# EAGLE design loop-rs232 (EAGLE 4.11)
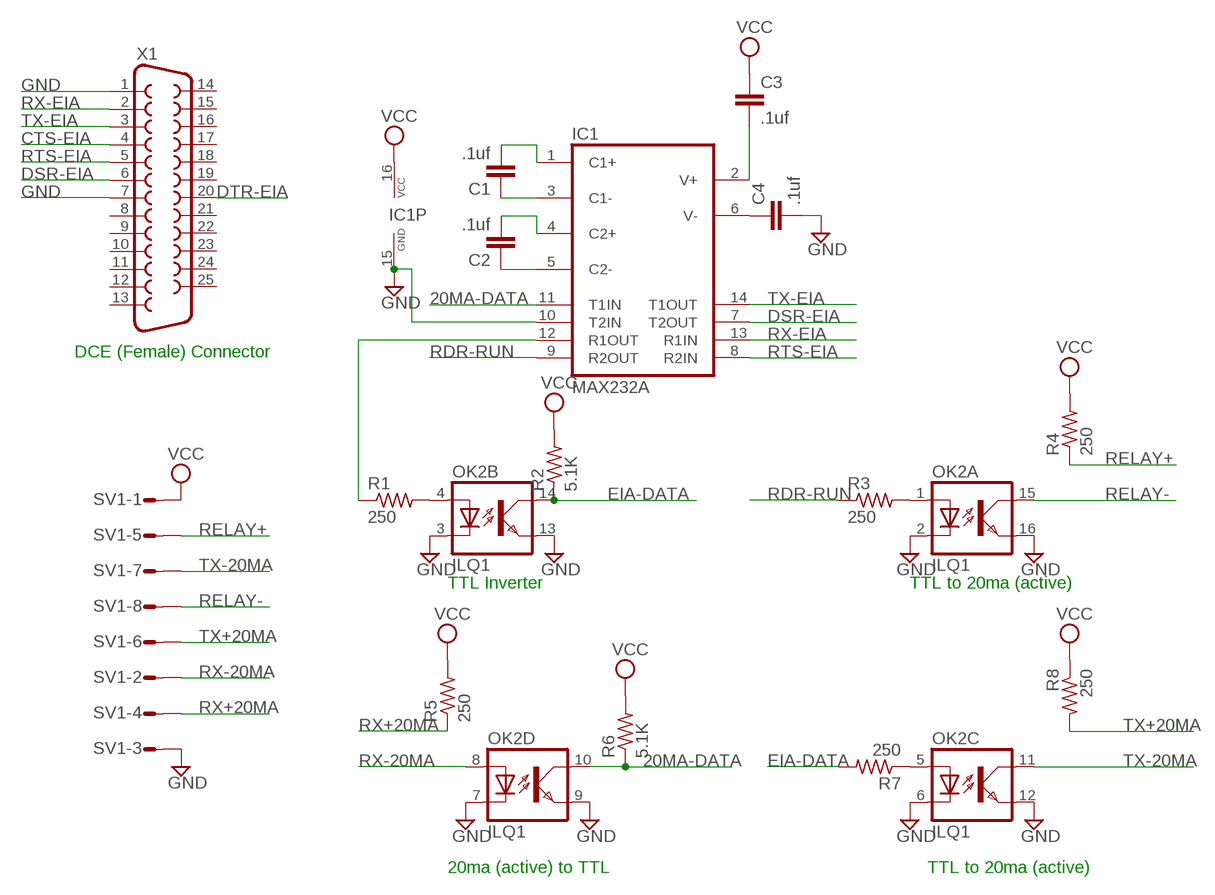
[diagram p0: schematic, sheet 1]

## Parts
C1  .1uf  C-EU050-025X075  [C050-025X075]
C2  .1uf  C-EU050-025X075  [C050-025X075]
C3  .1uf  C-EU050-025X075  [C050-025X075]
C4  .1uf  C-EU050-025X075  [C050-025X075]
IC1  MAX232A  MAX232  [DIL16]
OK2  ILQ1  [DIL16]
R1  250  R-US_0207/10  [0207/10]
R2  5.1K  R-US_0207/10  [0207/10]
R3  250  R-US_0207/10  [0207/10]
R4  250  R-US_0207/10  [0207/10]
R5  250  R-US_0207/10  [0207/10]
R6  5.1K  R-US_0207/10  [0207/10]
R7  250  R-US_0207/10  [0207/10]
R8  250  R-US_0207/10  [0207/10]
SV1  S08P  [S08P]
X1  F25H  [F25H]

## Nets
20MA-DATA: IC1.11(T1IN) OK2.10(D:COL) R6.1
CTS-EIA: X1.4
DSR-EIA: IC1.7(T2OUT) X1.6
DTR-EIA: X1.20
EIA-DATA: OK2.14(B:COL) R2.1 R7.2
GND: C4.2 IC1.10(T2IN) IC1.15(GND) OK2.2(A:C) OK2.3(B:C) OK2.6(C:C) OK2.7(D:C) OK2.9(D:EMIT) OK2.12(C:EMIT) OK2.13(B:EMIT) OK2.16(A:EMIT) SV1.3 X1.1 X1.7
N$1: C2.1 IC1.5(C2-)
N$2: C2.2 IC1.4(C2+)
N$3: C1.2 IC1.1(C1+)
N$4: C1.1 IC1.3(C1-)
N$8: IC1.12(R1OUT) R1.1
N$9: C3.2 IC1.2(V+)
N$10: C4.1 IC1.6(V-)
N$11: OK2.4(B:A) R1.2
N$12: OK2.1(A:A) R3.2
N$15: OK2.5(C:A) R7.1
RDR-RUN: IC1.9(R2OUT) R3.1
RELAY+: R4.1 SV1.5
RELAY-: OK2.15(A:COL) SV1.8
RTS-EIA: IC1.8(R2IN) X1.5
RX+20MA: R5.1 SV1.4
RX-20MA: OK2.8(D:A) SV1.2
RX-EIA: IC1.13(R1IN) X1.2
TX+20MA: R8.2 SV1.6
TX-20MA: OK2.11(C:COL) SV1.7
TX-EIA: IC1.14(T1OUT) X1.3
VCC: C3.1 IC1.16(VCC) R2.2 R4.2 R5.2 R6.2 R8.1 SV1.1
Unconnected: X1.8 X1.9 X1.10 X1.11 X1.12 X1.13 X1.14 X1.15 X1.16 X1.17 X1.18 X1.19 X1.21 X1.22 X1.23 X1.24 X1.25

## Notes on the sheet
- DCE (Female) Connector
- TTL Inverter | TTL to 20ma (active)
- 20ma (active) to TTL | TTL to 20ma (active)

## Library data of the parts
C1-C4 = rcl:C-EU: CAPACITOR, European symbol
IC1 = maxim:MAX232: RS232 TRANSEIVER
OK2 = optocoupler:ILQ1: SIEMENS OPTO COUPLER
R1-R8 = rcl:R-US_: RESISTOR, American symbol
SV1 = con-amp-mt:S08P: AMP MT CONNECTOR
X1 = con-subd:F25: SUB-D

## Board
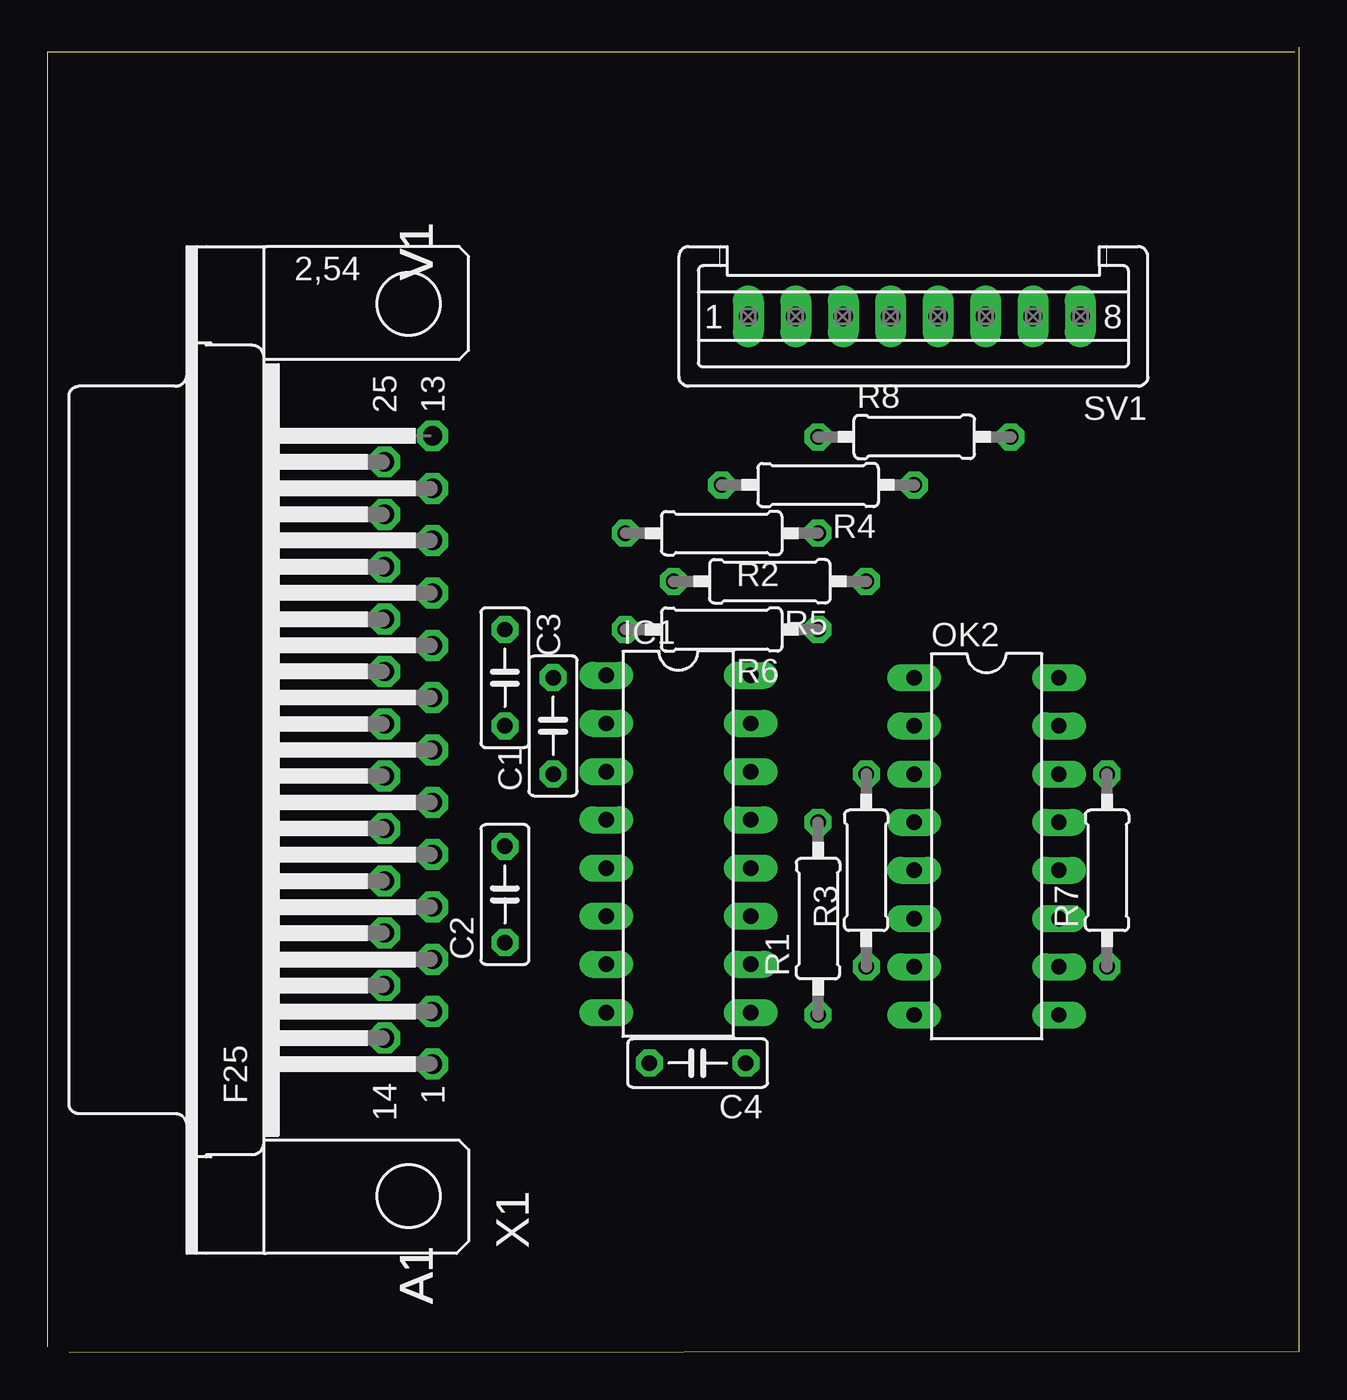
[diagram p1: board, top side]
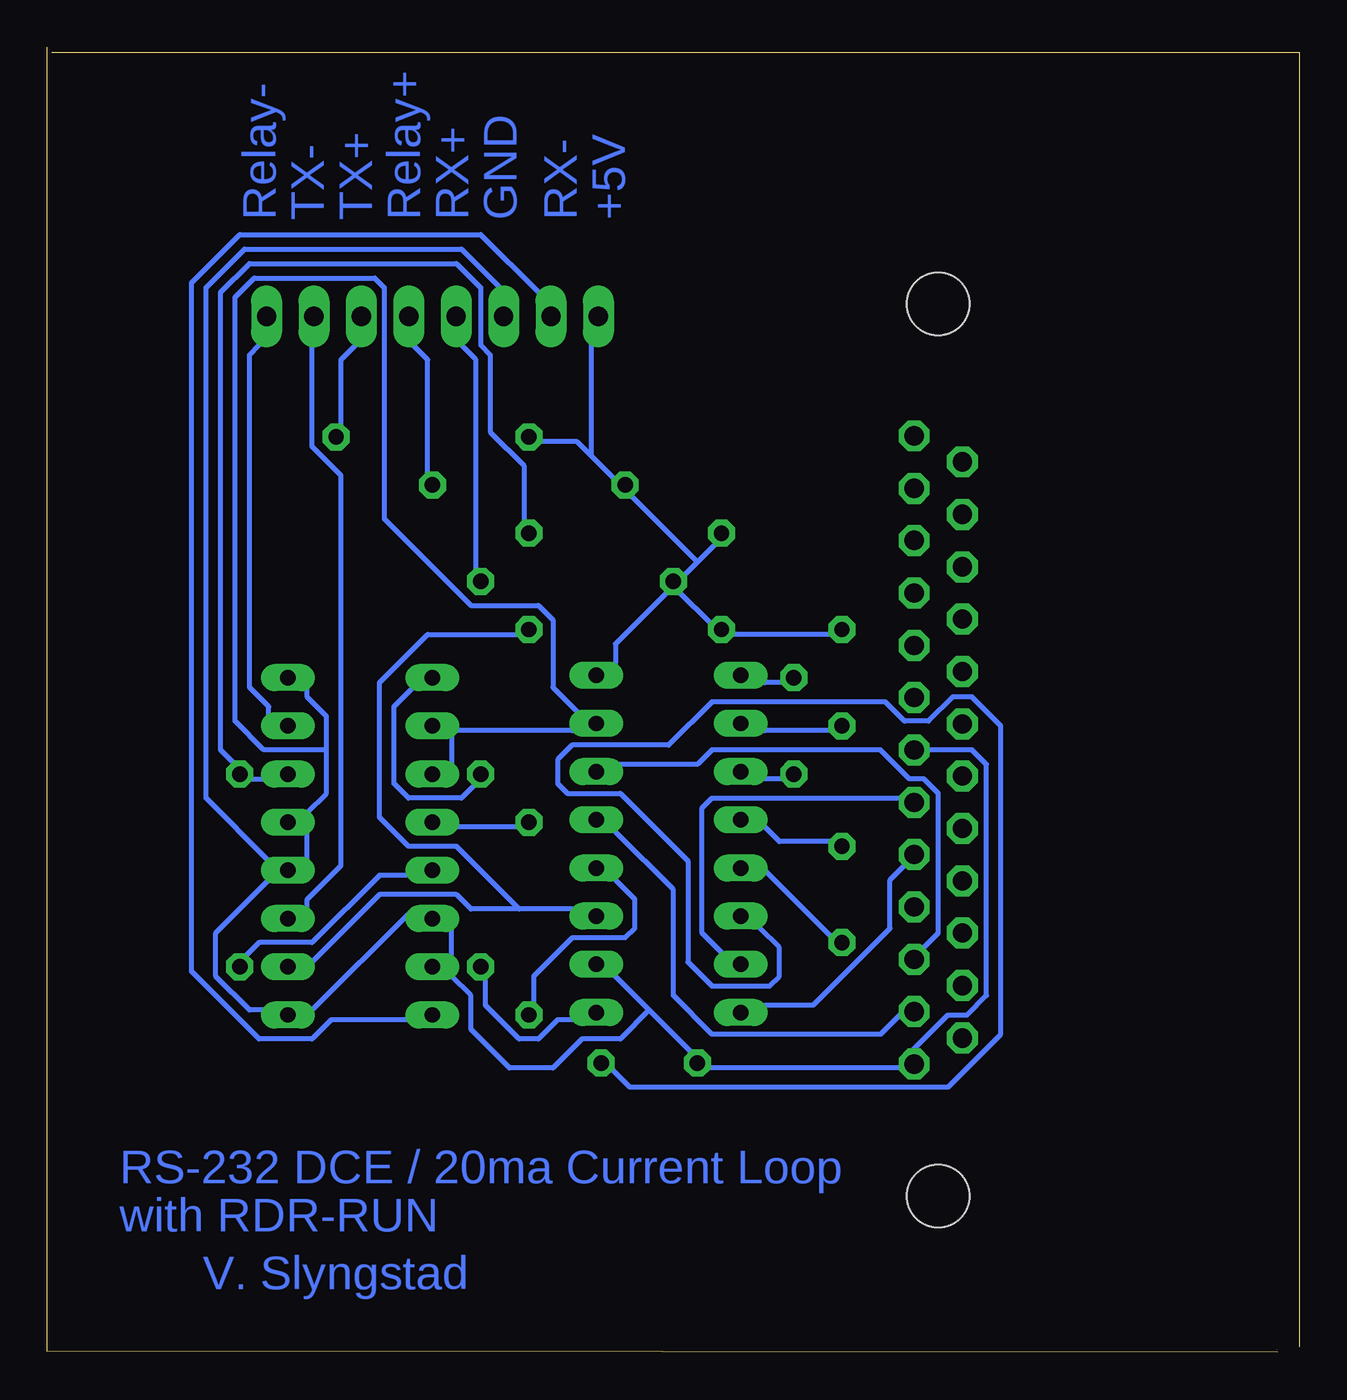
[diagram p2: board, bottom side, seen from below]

Size 66.02 x 68.8 mm. Coordinates in mm from the lower left corner, seen from the top.
Outline: 1.14,0 66.02,0.04 66.02,68.8
Outline: 65.78,68.54 0,68.54 0,0.29
Copper layers (1*16): Top 0.035mm / dielectric 1.5mm / Bottom 0.035mm
Design rules "10mils": minimum track width 10mil, minimum drill 28mil, track to track 15mil, track to pad 10mil, pad to pad 10mil, via to via 10mil, smd to smd 10mil, copper to edge 40mil, drill to drill 10mil, minimum pad ring 12mil, minimum via ring 8mil, stop-mask expansion 0mil, vias tented up to drill 0mil, thermal gap 10mil

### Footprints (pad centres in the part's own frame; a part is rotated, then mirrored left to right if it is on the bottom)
C050-025X075 = drill 0.813 octagon: 1 -2.54,0; 2 2.54,0
DIL16 = drill 0.813 long: 1 -8.89,-3.81; 2 -6.35,-3.81; 3 -3.81,-3.81; 4 -1.27,-3.81; 5 1.27,-3.81; 6 3.81,-3.81; 7 6.35,-3.81; 8 8.89,-3.81; 9 8.89,3.81; 10 6.35,3.81; 11 3.81,3.81; 12 1.27,3.81; 13 -1.27,3.81; 14 -3.81,3.81; 15 -6.35,3.81; 16 -8.89,3.81
0207/10 = drill 0.813 octagon: 1 -5.08,0; 2 5.08,0
S08P = drill 1.016 long: 1 8.75,0; 2 6.25,0; 3 3.75,0; 4 1.25,0; 5 -1.25,0; 6 -3.75,0; 7 -6.25,0; 8 -8.75,0
F25H = drill 1.016 octagon: 1 -16.561,-1.27; 2 -13.792,-1.27; 3 -11.049,-1.27; 4 -8.28,-1.27; 5 -5.512,-1.27; 6 -2.769,-1.27; 7 0,-1.27; 8 2.769,-1.27; 9 5.512,-1.27; 10 8.28,-1.27; 11 11.049,-1.27; 12 13.792,-1.27; 13 16.561,-1.27; 14 -15.189,1.27; 15 -12.421,1.27; 16 -9.652,1.27; 17 -6.909,1.27; 18 -4.14,1.27; 19 -1.372,1.27; 20 1.372,1.27; 21 4.14,1.27; 22 6.909,1.27; 23 9.652,1.27; 24 12.421,1.27; 25 15.189,1.27 | hole 3.302: -23.52,0; 23.52,0

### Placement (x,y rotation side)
C1  26.67,33.02 90 top
C2  24.12,24.13 90 top
C3  24.12,35.56 270 top
C4  34.28,15.24 180 top
IC1  33.27,26.8 270 top
OK2  49.52,26.67 270 top
R1  40.63,22.86 90 top
R2  35.55,43.18 180 top
R3  43.17,25.4 90 top
R4  40.63,45.72 180 top
R5  38.09,40.64 180 top
R6  35.55,38.1 180 top
R7  55.88,25.4 90 top
R8  45.71,48.26 0 top
SV1  45.71,54.61 180 top
X1  19.05,31.75 90 top

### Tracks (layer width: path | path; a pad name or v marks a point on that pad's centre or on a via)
20MA-DATA
  Bottom 0.254: 41.14,23.37 43.68,23.37 44.45,24.13 48.51,24.13 52.06,20.57 OK2.10 | 41.14,23.37 38.35,23.37 IC1.11 | 41.14,23.37 44.45,26.67 46.98,26.67 48.51,28.19 48.51,35.31 45.97,37.85 41.14,37.85 R6.1
DSR-EIA
  Bottom 0.254: IC1.7 30.48,21.08 31.49,22.1 31.49,28.7 30.98,29.21 21.08,29.21 X1.6
EIA-DATA
  Bottom 0.254: OK2.14 54.6,30.23 55.37,30.23 R7.2 56.13,30.99 56.89,31.75 56.89,55.88 55.37,57.4 44.45,57.4 43.17,56.13 43.17,53.09 42.67,52.58 42.67,48.51 40.89,46.74 40.89,43.69 R2.1
GND
  Bottom 0.254: 34.28,18.03 36.06,19.81 IC1.10 | 34.28,18.03 32,15.75 C4.2 31.24,14.99 21.08,14.99 X1.1 20.57,15.75 18.54,17.78 17.52,17.78 16.51,18.8 16.51,30.99 17.27,31.75 X1.7 | OK2.3 44.7,30.99 44.7,32.51 OK2.2 44.45,32.77 38.35,32.77 IC1.15 38.09,33.78 39.36,35.05 39.36,38.61 40.13,39.37 43.68,39.37 48.25,43.94 48.25,56.13 48.76,56.64 55.11,56.64 56.13,55.63 56.13,33.27 54.6,31.75 51.3,31.75 | OK2.12 52.32,25.91 52.32,27.43 OK2.13 52.32,28.45 51.3,29.46 51.3,31.75 | 51.3,31.75 51.3,33.53 52.32,34.54 52.32,35.05 OK2.16 | SV1.3 42.16,56.13 44.19,58.17 55.62,58.17 57.65,56.13 57.65,29.21 54.35,25.91 OK2.12 | OK2.12 54.35,24.89 57.14,22.1 57.14,19.81 55.37,18.03 54.6,18.03 OK2.9 52.06,18.03 46.98,23.11 OK2.6 44.7,22.35 44.7,20.83 OK2.7 44.7,19.81 43.68,18.8 43.68,17.02 41.65,14.99 39.36,14.99 37.84,16.51 35.81,16.51 34.28,18.03
N$1
  Bottom 0.254: C2.1 24.63,21.84 28.19,25.4 IC1.5
N$2
  Bottom 0.254: C2.2 24.63,26.92 27.43,26.92 28.19,27.69 IC1.4
N$3
  Bottom 0.254: C1.2 27.17,35.31 28.19,35.31 IC1.1
N$4
  Bottom 0.254: C1.1 27.17,30.23 28.19,30.23 IC1.3
N$8
  Bottom 0.254: R1.1 40.38,18.29 40.38,19.81 38.35,21.84 35.55,21.84 35.05,22.35 35.05,23.88 36.06,24.89 IC1.12
N$9
  Bottom 0.254: C3.2 24.63,32.77 28.19,32.77 IC1.2
N$10
  Bottom 0.254: IC1.6 28.44,22.35 27.43,21.34 27.43,19.81 27.94,19.3 30.98,19.3 32.25,20.57 32.25,25.91 35.81,29.46 38.6,29.46 39.11,29.97 39.11,31.24 38.35,32 33.27,32 30.98,34.29 21.84,34.29 20.82,33.27 19.55,33.27 18.28,34.54 17.27,34.54 15.74,33.02 15.74,16.76 18.54,13.97 35.3,13.97 36.32,14.99 C4.1
N$11
  Bottom 0.254: R1.2 41.14,27.69 44.45,27.69 OK2.4
N$12
  Bottom 0.254: R3.2 43.43,29.97 44.19,29.21 46.98,29.21 47.75,29.97 47.75,34.04 46.73,35.05 OK2.1
N$15
  Bottom 0.254: OK2.5 46.98,25.15 48.51,25.15 52.06,21.59 54.86,21.59 55.62,20.83 R7.1
RDR-RUN
  Bottom 0.254: IC1.9 38.35,17.53 39.11,17.53 40.13,16.51 41.14,16.51 42.92,18.29 42.92,19.81 R3.1
RELAY+
  Bottom 0.254: R4.1 45.97,46.23 45.97,52.32 46.73,53.09 SV1.5
RELAY-
  Bottom 0.254: OK2.15 54.35,33.53 54.35,34.04 55.37,35.05 55.37,52.58 54.86,53.09 SV1.8
RTS-EIA
  Bottom 0.254: IC1.8 28.19,18.29 25.65,18.29 21.59,22.35 21.59,24.89 20.82,25.65 X1.5
RX+20MA
  Bottom 0.254: R5.1 43.43,41.15 43.43,52.32 44.19,53.09 SV1.4
RX-20MA
  Bottom 0.254: OK2.8 46.98,17.53 51.05,17.53 52.06,16.51 54.86,16.51 58.41,20.07 58.41,56.39 55.88,58.93 43.17,58.93 40.13,55.88 SV1.2
RX-EIA
  Bottom 0.254: IC1.13 36.06,27.43 33.02,24.38 33.02,18.8 30.98,16.76 22.09,16.76 21.08,17.78 X1.2
TX+20MA
  Bottom 0.254: R8.2 50.54,48.77 50.54,52.32 49.78,53.09 SV1.6
TX-20MA
  Bottom 0.254: OK2.11 52.32,23.37 52.32,23.88 50.54,25.65 50.54,46.23 52.06,47.75 52.06,53.09 SV1.7
TX-EIA
  Bottom 0.254: IC1.14 35.81,30.99 31.75,30.99 30.98,31.75 22.09,31.75 20.57,30.23 19.81,30.23 19.05,29.46 19.05,22.1 19.81,21.34 X1.3
VCC
  Bottom 0.254: C3.1 24.63,37.85 29.97,37.85 R6.2 30.98,38.35 32.76,40.13 R5.2 | IC1.16 36.06,36.32 36.06,37.34 33.27,40.13 R5.2 | 31.75,41.66 32.51,40.89 R5.2 | 31.75,41.66 30.73,42.67 R2.2 | 31.75,41.66 35.3,45.21 R4.2 36.06,45.97 37.33,47.24 | 37.33,47.24 38.09,48.01 40.13,48.01 R8.1 | 37.33,47.24 37.33,53.09 SV1.1

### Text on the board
Bottom: +5V | RX- | GND | RX+ | Relay+ | TX+ | TX- | Relay- | RS-232 DCE / 20ma Current Loop | with RDR-RUN | V. Slyngstad
tNames: V1 | V1 | V1 | V1 | V1 | V1 | V1 | V1 | V1 | V1 | V1 | V1 | V1 | V1 | V1 | V1 | V1 | V1 | V1 | V1 | V1 | V1 | V1 | V1 | V1 | V1 | V1 | V1 | V1 | V1 | V1 | V1 | A1 | A1 | A1 | A1 | A1 | A1 | A1 | A1 | A1 | A1 | A1 | A1 | A1 | A1 | A1 | A1 | A1 | A1 | A1 | A1 | A1 | A1 | A1 | A1 | A1 | A1 | A1 | A1 | A1 | A1 | A1 | A1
